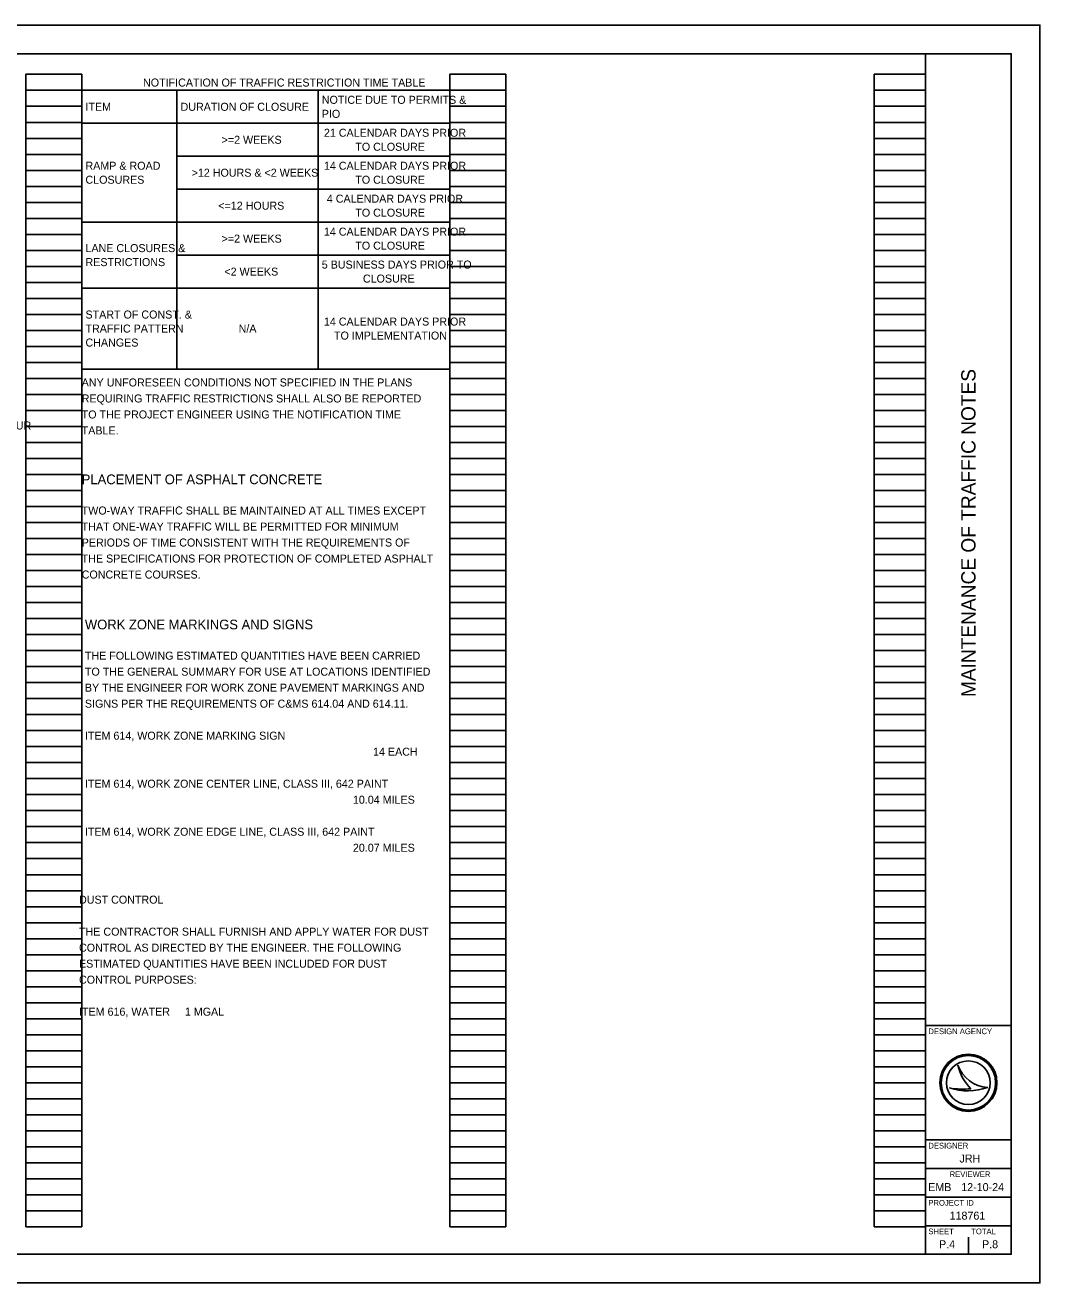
# Model space of a CAD drawing. Extents: x 0 to 34, y 0 to 22.
# Drawn here: x 16.25 to 34, y 0 to 22 of the extents above; entities that cross this region are included whole.
import ezdxf

# ---------------------------------------------------------------- set-up
doc = ezdxf.new("R2010")
doc.units = 0
for name, color, linetype in [('Default', 7, 'Continuous'), ('SH_Border', 7, 'Continuous'), ('SH_Cut_Line', 7, 'Continuous'), ('SH_Data', 7, 'Continuous'), ('SH_Text', 7, 'Continuous')]:
    doc.layers.add(name, color=color, linetype=linetype)

msp = doc.modelspace()

# ---------------------------------------------------------------- linework, layer by layer
at = {"layer": 'Default'}
for p, q in [((17.24, 20.86), (23.68, 20.86)), ((17.24, 20.86), (17.24, 15.985)), ((18.904, 20.86), (18.904, 15.985)), ((21.374, 20.86), (21.374, 15.985)), ((23.68, 20.86), (23.68, 15.985)), ((17.24, 20.284), (23.68, 20.284)), ((18.904, 19.707), (23.68, 19.707)), ((18.904, 19.131), (23.68, 19.131)), ((17.24, 18.554), (23.68, 18.554)), ((18.904, 17.978), (23.68, 17.978)), ((17.24, 17.401), (23.68, 17.401)), ((17.24, 15.985), (23.68, 15.985))]:
    msp.add_line(p, q, dxfattribs=at)
at = {"layer": 'SH_Border'}
for p, q in [((32, 0.5), (32, 21.5)), ((32, 4.5), (33.5, 4.5)), ((32, 2.5), (33.5, 2.5)), ((32, 2), (33.5, 2)), ((32, 1.5), (33.5, 1.5)), ((32, 1), (33.5, 1))]:
    msp.add_line(p, q, dxfattribs=at)
msp.add_lwpolyline([(1.5, 21.5), (33.5, 21.5), (33.5, 0.5), (1.5, 0.5)], close=True, dxfattribs=at)
at = {"layer": 'SH_Cut_Line'}
msp.add_lwpolyline([(0, 0), (34, 0), (34, 22), (0, 22)], close=True, dxfattribs=at)
at = {"layer": 'SH_Data'}
for p, q in [((16.26, 0.98), (16.26, 21.14)), ((16.26, 21.14), (17.24, 21.14)), ((17.24, 0.98), (17.24, 21.14)), ((23.68, 0.98), (23.68, 21.14)), ((23.68, 21.14), (24.66, 21.14)), ((24.66, 0.98), (24.66, 21.14)), ((31.1, 0.98), (31.1, 21.14)), ((31.1, 21.14), (32, 21.14)), ((32, 0.98), (32, 21.14)), ((16.26, 20.86), (17.24, 20.86)), ((23.68, 20.86), (24.66, 20.86)), ((31.1, 20.86), (32, 20.86)), ((16.26, 20.58), (17.24, 20.58)), ((23.68, 20.58), (24.66, 20.58)), ((31.1, 20.58), (32, 20.58)), ((16.26, 20.3), (17.24, 20.3)), ((23.68, 20.3), (24.66, 20.3)), ((31.1, 20.3), (32, 20.3)), ((16.26, 20.02), (17.24, 20.02)), ((23.68, 20.02), (24.66, 20.02)), ((31.1, 20.02), (32, 20.02)), ((16.26, 19.74), (17.24, 19.74)), ((23.68, 19.74), (24.66, 19.74)), ((31.1, 19.74), (32, 19.74)), ((16.26, 19.46), (17.24, 19.46)), ((23.68, 19.46), (24.66, 19.46)), ((31.1, 19.46), (32, 19.46)), ((16.26, 19.18), (17.24, 19.18)), ((23.68, 19.18), (24.66, 19.18)), ((31.1, 19.18), (32, 19.18)), ((16.26, 18.9), (17.24, 18.9)), ((23.68, 18.9), (24.66, 18.9)), ((31.1, 18.9), (32, 18.9)), ((16.26, 18.62), (17.24, 18.62)), ((23.68, 18.62), (24.66, 18.62)), ((31.1, 18.62), (32, 18.62)), ((16.26, 18.34), (17.24, 18.34)), ((23.68, 18.34), (24.66, 18.34)), ((31.1, 18.34), (32, 18.34)), ((16.26, 18.06), (17.24, 18.06)), ((23.68, 18.06), (24.66, 18.06)), ((31.1, 18.06), (32, 18.06)), ((16.26, 17.78), (17.24, 17.78)), ((23.68, 17.78), (24.66, 17.78)), ((31.1, 17.78), (32, 17.78)), ((16.26, 17.5), (17.24, 17.5)), ((23.68, 17.5), (24.66, 17.5)), ((31.1, 17.5), (32, 17.5)), ((16.26, 17.22), (17.24, 17.22)), ((23.68, 17.22), (24.66, 17.22)), ((31.1, 17.22), (32, 17.22)), ((16.26, 16.94), (17.24, 16.94)), ((23.68, 16.94), (24.66, 16.94)), ((31.1, 16.94), (32, 16.94)), ((16.26, 16.66), (17.24, 16.66)), ((23.68, 16.66), (24.66, 16.66)), ((31.1, 16.66), (32, 16.66)), ((16.26, 16.38), (17.24, 16.38)), ((23.68, 16.38), (24.66, 16.38)), ((31.1, 16.38), (32, 16.38)), ((16.26, 16.1), (17.24, 16.1)), ((23.68, 16.1), (24.66, 16.1)), ((31.1, 16.1), (32, 16.1)), ((16.26, 15.82), (17.24, 15.82)), ((23.68, 15.82), (24.66, 15.82)), ((31.1, 15.82), (32, 15.82)), ((16.26, 15.54), (17.24, 15.54)), ((23.68, 15.54), (24.66, 15.54)), ((31.1, 15.54), (32, 15.54)), ((16.26, 15.26), (17.24, 15.26)), ((23.68, 15.26), (24.66, 15.26)), ((31.1, 15.26), (32, 15.26)), ((16.26, 14.98), (17.24, 14.98)), ((23.68, 14.98), (24.66, 14.98)), ((31.1, 14.98), (32, 14.98)), ((16.26, 14.7), (17.24, 14.7)), ((23.68, 14.7), (24.66, 14.7)), ((31.1, 14.7), (32, 14.7)), ((16.26, 14.42), (17.24, 14.42)), ((23.68, 14.42), (24.66, 14.42)), ((31.1, 14.42), (32, 14.42)), ((16.26, 14.14), (17.24, 14.14)), ((23.68, 14.14), (24.66, 14.14)), ((31.1, 14.14), (32, 14.14)), ((16.26, 13.86), (17.24, 13.86)), ((23.68, 13.86), (24.66, 13.86)), ((31.1, 13.86), (32, 13.86)), ((16.26, 13.58), (17.24, 13.58)), ((23.68, 13.58), (24.66, 13.58)), ((31.1, 13.58), (32, 13.58)), ((16.26, 13.3), (17.24, 13.3)), ((23.68, 13.3), (24.66, 13.3)), ((31.1, 13.3), (32, 13.3)), ((16.26, 13.02), (17.24, 13.02)), ((23.68, 13.02), (24.66, 13.02)), ((31.1, 13.02), (32, 13.02)), ((16.26, 12.74), (17.24, 12.74)), ((23.68, 12.74), (24.66, 12.74)), ((31.1, 12.74), (32, 12.74)), ((16.26, 12.46), (17.24, 12.46)), ((23.68, 12.46), (24.66, 12.46)), ((31.1, 12.46), (32, 12.46)), ((16.26, 12.18), (17.24, 12.18)), ((23.68, 12.18), (24.66, 12.18)), ((31.1, 12.18), (32, 12.18)), ((16.26, 11.9), (17.24, 11.9)), ((23.68, 11.9), (24.66, 11.9)), ((31.1, 11.9), (32, 11.9)), ((16.26, 11.62), (17.24, 11.62)), ((23.68, 11.62), (24.66, 11.62)), ((31.1, 11.62), (32, 11.62)), ((16.26, 11.34), (17.24, 11.34)), ((23.68, 11.34), (24.66, 11.34)), ((31.1, 11.34), (32, 11.34)), ((16.26, 11.06), (17.24, 11.06)), ((23.68, 11.06), (24.66, 11.06)), ((31.1, 11.06), (32, 11.06)), ((16.26, 10.78), (17.24, 10.78)), ((23.68, 10.78), (24.66, 10.78)), ((31.1, 10.78), (32, 10.78)), ((16.26, 10.5), (17.24, 10.5)), ((23.68, 10.5), (24.66, 10.5)), ((31.1, 10.5), (32, 10.5)), ((16.26, 10.22), (17.24, 10.22)), ((23.68, 10.22), (24.66, 10.22)), ((31.1, 10.22), (32, 10.22)), ((16.26, 9.94), (17.24, 9.94)), ((23.68, 9.94), (24.66, 9.94)), ((31.1, 9.94), (32, 9.94)), ((16.26, 9.66), (17.24, 9.66)), ((23.68, 9.66), (24.66, 9.66)), ((31.1, 9.66), (32, 9.66)), ((16.26, 9.38), (17.24, 9.38)), ((23.68, 9.38), (24.66, 9.38)), ((31.1, 9.38), (32, 9.38)), ((16.26, 9.1), (17.24, 9.1)), ((23.68, 9.1), (24.66, 9.1)), ((31.1, 9.1), (32, 9.1)), ((16.26, 8.82), (17.24, 8.82)), ((23.68, 8.82), (24.66, 8.82)), ((31.1, 8.82), (32, 8.82)), ((16.26, 8.54), (17.24, 8.54)), ((23.68, 8.54), (24.66, 8.54)), ((31.1, 8.54), (32, 8.54)), ((16.26, 8.26), (17.24, 8.26)), ((23.68, 8.26), (24.66, 8.26)), ((31.1, 8.26), (32, 8.26)), ((16.26, 7.98), (17.24, 7.98)), ((23.68, 7.98), (24.66, 7.98)), ((31.1, 7.98), (32, 7.98)), ((16.26, 7.7), (17.24, 7.7)), ((23.68, 7.7), (24.66, 7.7)), ((31.1, 7.7), (32, 7.7)), ((16.26, 7.42), (17.24, 7.42)), ((23.68, 7.42), (24.66, 7.42)), ((31.1, 7.42), (32, 7.42)), ((16.26, 7.14), (17.24, 7.14)), ((23.68, 7.14), (24.66, 7.14)), ((31.1, 7.14), (32, 7.14)), ((16.26, 6.86), (17.24, 6.86)), ((23.68, 6.86), (24.66, 6.86)), ((31.1, 6.86), (32, 6.86)), ((16.26, 6.58), (17.24, 6.58)), ((23.68, 6.58), (24.66, 6.58)), ((31.1, 6.58), (32, 6.58)), ((16.26, 6.3), (17.24, 6.3)), ((23.68, 6.3), (24.66, 6.3)), ((31.1, 6.3), (32, 6.3)), ((16.26, 6.02), (17.24, 6.02)), ((23.68, 6.02), (24.66, 6.02)), ((31.1, 6.02), (32, 6.02)), ((16.26, 5.74), (17.24, 5.74)), ((23.68, 5.74), (24.66, 5.74)), ((31.1, 5.74), (32, 5.74)), ((16.26, 5.46), (17.24, 5.46)), ((23.68, 5.46), (24.66, 5.46)), ((31.1, 5.46), (32, 5.46)), ((16.26, 5.18), (17.24, 5.18)), ((23.68, 5.18), (24.66, 5.18)), ((31.1, 5.18), (32, 5.18)), ((16.26, 4.9), (17.24, 4.9)), ((23.68, 4.9), (24.66, 4.9)), ((31.1, 4.9), (32, 4.9)), ((16.26, 4.62), (17.24, 4.62)), ((23.68, 4.62), (24.66, 4.62)), ((31.1, 4.62), (32, 4.62)), ((16.26, 4.34), (17.24, 4.34)), ((23.68, 4.34), (24.66, 4.34)), ((31.1, 4.34), (32, 4.34)), ((16.26, 4.06), (17.24, 4.06)), ((23.68, 4.06), (24.66, 4.06)), ((31.1, 4.06), (32, 4.06)), ((16.26, 3.78), (17.24, 3.78)), ((23.68, 3.78), (24.66, 3.78)), ((31.1, 3.78), (32, 3.78)), ((32.567, 3.81), (32.567, 3.81)), ((16.26, 3.5), (17.24, 3.5)), ((23.68, 3.5), (24.66, 3.5)), ((31.1, 3.5), (32, 3.5)), ((32.417, 3.41), (32.417, 3.41)), ((32.75, 3.5), (32.75, 3.5)), ((33.087, 3.419), (33.087, 3.419)), ((16.26, 3.22), (17.24, 3.22)), ((23.68, 3.22), (24.66, 3.22)), ((31.1, 3.22), (32, 3.22)), ((16.26, 2.94), (17.24, 2.94)), ((23.68, 2.94), (24.66, 2.94)), ((31.1, 2.94), (32, 2.94)), ((16.26, 2.66), (17.24, 2.66)), ((23.68, 2.66), (24.66, 2.66)), ((31.1, 2.66), (32, 2.66)), ((16.26, 2.38), (17.24, 2.38)), ((23.68, 2.38), (24.66, 2.38)), ((31.1, 2.38), (32, 2.38)), ((16.26, 2.1), (17.24, 2.1)), ((23.68, 2.1), (24.66, 2.1)), ((31.1, 2.1), (32, 2.1)), ((16.26, 1.82), (17.24, 1.82)), ((23.68, 1.82), (24.66, 1.82)), ((31.1, 1.82), (32, 1.82)), ((16.26, 1.54), (17.24, 1.54)), ((23.68, 1.54), (24.66, 1.54)), ((31.1, 1.54), (32, 1.54)), ((16.26, 1.26), (17.24, 1.26)), ((23.68, 1.26), (24.66, 1.26)), ((31.1, 1.26), (32, 1.26)), ((16.26, 0.98), (17.24, 0.98)), ((23.68, 0.98), (24.66, 0.98)), ((31.1, 0.98), (32, 0.98)), ((32.375, 0.675), (32.375, 0.675)), ((32.75, 0.5), (32.75, 0.8))]:
    msp.add_line(p, q, dxfattribs=at)
for radius in [0.5, 0.477, 0.477, 0.382]:
    msp.add_circle((32.75, 3.5), radius, dxfattribs=at)
for centre, radius, start, end in [((33.116, 3.998), 0.58, 198.9257, 198.9319), ((33.347, 3.97), 0.796, 191.6379, 191.6421), ((33.116, 3.998), 0.58, 198.9319, 267.1657), ((33.347, 3.97), 0.796, 191.6421, 226.0947), ((32.739, 4.37), 1.013, 251.4576, 290.0832), ((32.648, 4.654), 1.266, 259.4964, 259.4995), ((32.739, 4.37), 1.013, 251.4527, 251.4576), ((32.648, 4.654), 1.266, 259.4995, 276.6672)]:
    msp.add_arc(centre, radius, start, end, dxfattribs=at)

# ---------------------------------------------------------------- texts
at = {"layer": 'Default'}
for s, p in [('NOTIFICATION OF TRAFFIC RESTRICTION TIME TABLE', (18.313, 20.926)), ('NOTICE DUE TO PERMITS & ', (21.44, 20.624)), ('ITEM', (17.306, 20.502)), ('DURATION OF CLOSURE', (18.969, 20.502)), ('PIO', (21.44, 20.379)), ('>=2 WEEKS', (19.687, 19.925)), ('21 CALENDAR DAYS PRIOR ', (21.477, 20.048)), ('TO CLOSURE', (22.026, 19.803)), ('RAMP & ROAD ', (17.306, 19.471)), ('14 CALENDAR DAYS PRIOR ', (21.477, 19.471)), ('CLOSURES', (17.306, 19.226)), ('>12 HOURS & <2 WEEKS', (19.163, 19.349)), ('TO CLOSURE', (22.026, 19.226)), ('4 CALENDAR DAYS PRIOR ', (21.528, 18.895)), ('<=12 HOURS', (19.629, 18.772)), ('TO CLOSURE', (22.026, 18.65)), ('>=2 WEEKS', (19.687, 18.196)), ('14 CALENDAR DAYS PRIOR ', (21.477, 18.318)), ('LANE CLOSURES & ', (17.306, 18.03)), ('TO CLOSURE', (22.026, 18.073)), ('RESTRICTIONS', (17.306, 17.785)), ('5 BUSINESS DAYS PRIOR TO ', (21.439, 17.742)), ('<2 WEEKS', (19.736, 17.619)), ('CLOSURE', (22.159, 17.497)), ('START OF CONST. & ', (17.306, 16.868)), ('TRAFFIC PATTERN ', (17.306, 16.623)), ('N/A', (19.985, 16.623)), ('14 CALENDAR DAYS PRIOR ', (21.477, 16.745)), ('CHANGES', (17.306, 16.378)), ('TO IMPLEMENTATION', (21.653, 16.5))]:
    msp.add_text(s, height=0.14, dxfattribs=at).set_placement(p)
at = {"layer": 'SH_Data'}
msp.add_text('MAINTENANCE OF TRAFFIC NOTES', height=0.25, rotation=90, dxfattribs=at).set_placement((32.875, 10.247))
for s, height, p in [('DESIGN AGENCY', 0.1, (32.05, 4.35)), ('DESIGNER', 0.1, (32.05, 2.35)), ('JRH', 0.14, (32.595, 2.105)), ('REVIEWER', 0.1, (32.422, 1.85)), ('EMB', 0.14, (32.047, 1.605)), ('12-10-24', 0.14, (32.625, 1.605)), ('PROJECT ID', 0.1, (32.05, 1.35)), ('118761', 0.14, (32.421, 1.105)), ('SHEET', 0.1, (32.05, 0.85)), ('TOTAL', 0.1, (32.8, 0.85)), ('P.4', 0.14, (32.237, 0.605)), ('P.8', 0.14, (32.989, 0.605))]:
    msp.add_text(s, height=height, dxfattribs=at).set_placement(p)
at = {"layer": 'SH_Text'}
for s, height, p in [('ANY UNFORESEEN CONDITIONS NOT SPECIFIED IN THE PLANS', 0.14, (17.24, 15.68)), ('REQUIRING TRAFFIC RESTRICTIONS SHALL ALSO BE REPORTED', 0.14, (17.24, 15.4)), ('TO THE PROJECT ENGINEER USING THE NOTIFICATION TIME', 0.14, (17.24, 15.12)), ('OF A PERSON OR PERSONS WHO CAN BE CONTACTED TWENTY-FOUR', 0.14, (9.867, 14.927)), ('TABLE.', 0.14, (17.24, 14.84)), ('PLACEMENT OF ASPHALT CONCRETE', 0.17, (17.24, 13.97)), ('TWO-WAY TRAFFIC SHALL BE MAINTAINED AT ALL TIMES EXCEPT', 0.14, (17.24, 13.44)), ('THAT ONE-WAY TRAFFIC WILL BE PERMITTED FOR MINIMUM', 0.14, (17.24, 13.16)), ('PERIODS OF TIME CONSISTENT WITH THE REQUIREMENTS OF', 0.14, (17.24, 12.88)), ('THE SPECIFICATIONS FOR PROTECTION OF COMPLETED ASPHALT', 0.14, (17.24, 12.6)), ('CONCRETE COURSES.', 0.14, (17.24, 12.32)), ('WORK ZONE MARKINGS AND SIGNS', 0.17, (17.296, 11.431)), ('THE FOLLOWING ESTIMATED QUANTITIES HAVE BEEN CARRIED', 0.14, (17.296, 10.901)), ('TO THE GENERAL SUMMARY FOR USE AT LOCATIONS IDENTIFIED', 0.14, (17.296, 10.621)), ('BY THE ENGINEER FOR WORK ZONE PAVEMENT MARKINGS AND', 0.14, (17.296, 10.341)), ('SIGNS PER THE REQUIREMENTS OF C&MS 614.04 AND 614.11.', 0.14, (17.296, 10.061)), ('ITEM 614, WORK ZONE MARKING SIGN', 0.14, (17.296, 9.501)), ('14 EACH', 0.14, (22.336, 9.221)), ('ITEM 614, WORK ZONE CENTER LINE, CLASS III, 642 PAINT', 0.14, (17.296, 8.661)), ('    10.04 MILES', 0.14, (21.776, 8.381)), ('ITEM 614, WORK ZONE EDGE LINE, CLASS III, 642 PAINT', 0.14, (17.296, 7.821)), ('    20.07 MILES', 0.14, (21.776, 7.541)), ('DUST CONTROL', 0.14, (17.193, 6.633)), ('THE CONTRACTOR SHALL FURNISH AND APPLY WATER FOR DUST', 0.14, (17.193, 6.073)), ('CONTROL AS DIRECTED BY THE ENGINEER. THE FOLLOWING', 0.14, (17.193, 5.793)), ('ESTIMATED QUANTITIES HAVE BEEN INCLUDED FOR DUST', 0.14, (17.193, 5.513)), ('CONTROL PURPOSES:', 0.14, (17.193, 5.233)), ('ITEM 616, WATER     1 MGAL', 0.14, (17.193, 4.673))]:
    msp.add_text(s, height=height, dxfattribs=at).set_placement(p)

doc.saveas('drawing.dxf')
